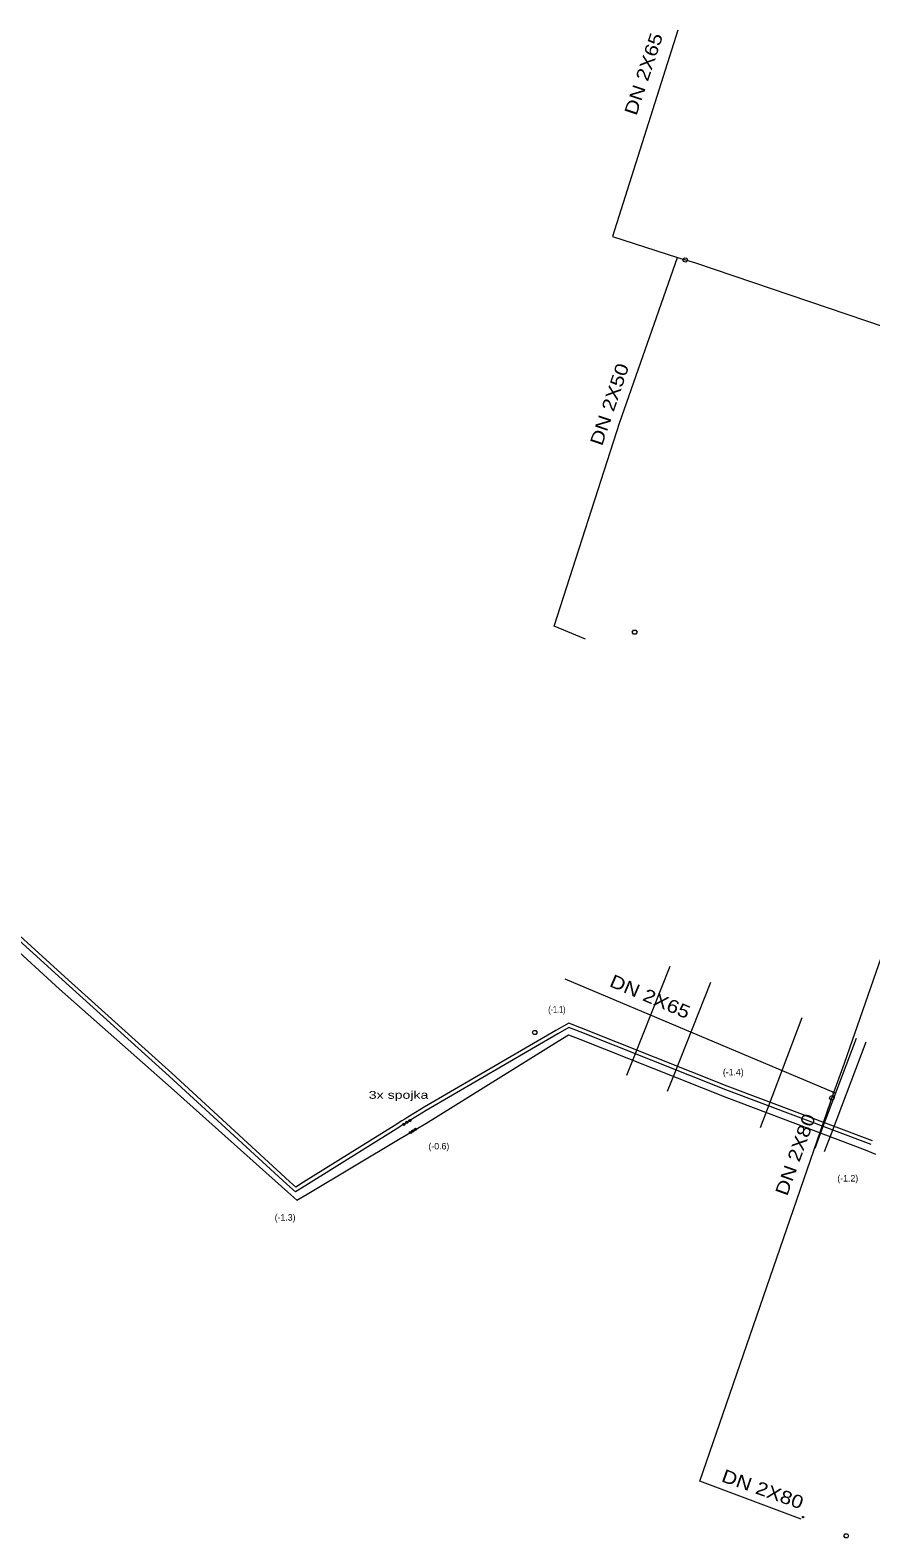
# Model space of a CAD drawing. Extents: x -725606 to -725269, y -977352 to -977136.
# Drawn here: x -725435.3 to -725370.8, y -977352.2 to -977236.5 of the extents above; entities that cross this region are included whole.
import ezdxf
from ezdxf.enums import TextEntityAlignment as Align

# ---------------------------------------------------------------- set-up
doc = ezdxf.new("R2010")
doc.units = 0
doc.header["$LTSCALE"] = 0.2
doc.header["$PDMODE"] = 32
doc.header["$PDSIZE"] = 0.1
for name, color, linetype, lineweight in [('45', 7, 'Continuous', 13), ('47', 7, 'Continuous', 13), ('48', 7, 'Continuous', 13), ('63', 7, 'Continuous', 13)]:
    doc.layers.add(name, color=color, linetype=linetype, lineweight=lineweight)
doc.layers.add('46', color=7, linetype='Continuous')
doc.layers.add('7', color=7, linetype='Continuous')

msp = doc.modelspace()

# ---------------------------------------------------------------- linework, layer by layer
at = {"layer": '45'}
for points in [[(-725379.25, -977320.68), (-725378.72, -977319.28), (-725376.07, -977312.26)], [(-725375.07, -977322.26), (-725374.54, -977320.86), (-725371.89, -977313.85)]]:
    msp.add_lwpolyline(points, dxfattribs=at)
at = {"layer": '47'}
msp.add_lwpolyline([(-725374.34, -977322.54), (-725373.81, -977321.14), (-725371.16, -977314.12)], dxfattribs=at)
at = {"layer": '48'}
for points in [[(-725389.5, -977316.68), (-725388.95, -977315.28), (-725386.19, -977308.31)], [(-725386.38, -977317.91), (-725385.83, -977316.52), (-725383.07, -977309.55)]]:
    msp.add_lwpolyline(points, dxfattribs=at)
at = {"layer": '63'}
for points in [[(-725385.587, -977236.544), (-725390.601, -977252.373), (-725385.627, -977253.982)], [(-725392.672, -977283.251), (-725395.077, -977282.248), (-725390.042, -977266.604), (-725385.627, -977253.982), (-725384.245, -977254.395), (-725355.226, -977264.237)], [(-725373.641, -977318.016), (-725372.809, -977315.746), (-725362.524, -977286.239), (-725361.335, -977286.635), (-725354.58, -977288.386)], [(-725370.76, -977321.99), (-725381.91, -977317.79), (-725393.08, -977313.36), (-725393.94, -977313.02), (-725394.79, -977313.51), (-725404.89, -977319.38), (-725405.55, -977319.79), (-725406.15, -977320.16), (-725406.38, -977320.3), (-725406.6, -977320.44), (-725407.19, -977320.81), (-725414.13, -977325.14), (-725414.92, -977325.63), (-725415.57, -977325.04), (-725424.61, -977316.74), (-725432.8, -977309.35), (-725441.73, -977301.26)], [(-725370.654, -977321.709), (-725381.802, -977317.51), (-725392.97, -977313.081), (-725393.964, -977312.688), (-725394.94, -977313.25), (-725405.045, -977319.123), (-725405.708, -977319.535), (-725406.307, -977319.904), (-725406.539, -977320.045), (-725406.76, -977320.186), (-725407.349, -977320.556), (-725414.288, -977324.885), (-725414.886, -977325.256), (-725415.368, -977324.818), (-725424.408, -977316.518), (-725432.599, -977309.127), (-725441.529, -977301.037)], [(-725441.74, -977302.1), (-725433.01, -977310.07), (-725424.46, -977317.64), (-725415.51, -977325.64), (-725414.81, -977326.26), (-725414.02, -977325.79), (-725406.88, -977321.53), (-725406.1, -977321.07), (-725405.91, -977320.95), (-725405.71, -977320.83), (-725404.93, -977320.37), (-725394.78, -977314.08), (-725393.97, -977313.58), (-725393.11, -977313.92), (-725381.9, -977318.36), (-725371.23, -977322.41), (-725370.43, -977322.72)], [(-725376.137, -977350.717), (-725383.903, -977347.814), (-725373.641, -977318.016), (-725394.234, -977309.306)]]:
    msp.add_lwpolyline(points, dxfattribs=at)
for points in [[(-725385.146, -977254.286), (-725385.197, -977254.119), (-725385.073, -977253.995), (-725384.899, -977254.039), (-725384.848, -977254.206), (-725384.971, -977254.33)], [(-725388.813, -977282.562), (-725388.723, -977282.712), (-725388.813, -977282.862), (-725388.993, -977282.862), (-725389.083, -977282.712), (-725388.993, -977282.562)], [(-725396.476, -977313.258), (-725396.386, -977313.408), (-725396.476, -977313.558), (-725396.656, -977313.558), (-725396.746, -977313.408), (-725396.656, -977313.258)], [(-725373.664, -977318.546), (-725373.835, -977318.584), (-725373.949, -977318.451), (-725373.892, -977318.281), (-725373.721, -977318.243), (-725373.607, -977318.376)], [(-725406.379, -977320.213), (-725406.303, -977320.254), (-725406.303, -977320.342), (-725406.381, -977320.387), (-725406.457, -977320.346), (-725406.457, -977320.258)], [(-725406.149, -977320.073), (-725406.073, -977320.114), (-725406.073, -977320.202), (-725406.151, -977320.247), (-725406.227, -977320.206), (-725406.227, -977320.118)], [(-725406.599, -977320.353), (-725406.523, -977320.394), (-725406.523, -977320.482), (-725406.601, -977320.527), (-725406.677, -977320.486), (-725406.677, -977320.398)], [(-725406.099, -977320.983), (-725406.023, -977321.024), (-725406.023, -977321.112), (-725406.101, -977321.157), (-725406.177, -977321.116), (-725406.177, -977321.028)], [(-725405.909, -977320.863), (-725405.833, -977320.904), (-725405.833, -977320.992), (-725405.911, -977321.037), (-725405.987, -977320.996), (-725405.987, -977320.908)], [(-725405.709, -977320.743), (-725405.633, -977320.784), (-725405.633, -977320.872), (-725405.711, -977320.917), (-725405.787, -977320.876), (-725405.787, -977320.788)], [(-725372.587, -977351.853), (-725372.497, -977352.003), (-725372.587, -977352.153), (-725372.767, -977352.153), (-725372.857, -977352.003), (-725372.767, -977351.853)]]:
    msp.add_lwpolyline(points, close=True, dxfattribs=at)
for p in [(-725373.641, -977318.016), (-725375.99, -977350.56)]:
    msp.add_point(p, dxfattribs=at)

# ---------------------------------------------------------------- texts
at = {"layer": '46', "width": 0.8}
msp.add_text('(-1.1)', height=0.5, dxfattribs=at).set_placement((-725394.87, -977311.88), align=Align.CENTER)
at = {"layer": '46'}
for s, p in [('(-1.4)', (-725381.34, -977316.69)), ('(-0.6)', (-725403.92, -977322.37)), ('(-1.2)', (-725372.56, -977324.83)), ('(-1.3)', (-725415.71, -977327.83))]:
    msp.add_text(s, height=0.5, dxfattribs=at).set_placement(p, align=Align.CENTER)
at = {"layer": '63', "width": 1.2}
for s, rotation, p in [('DN 2X65', 71.562, (-725387.7442, -977240.0611)), ('DN 2X50', 71.276, (-725390.3616, -977265.3945)), ('DN 2X65', 336.956, (-725387.9152, -977311.1067)), ('DN 2X80', 70.187, (-725376.1088, -977322.9335)), ('DN 2X80', 340.566, (-725379.2504, -977348.8904))]:
    msp.add_text(s, height=1, rotation=rotation, dxfattribs=at).set_placement(p, align=Align.CENTER)
at = {"layer": '7', "width": 1.35}
msp.add_text('3x spojka', height=0.6, dxfattribs=at).set_placement((-725407.0085, -977318.487), align=Align.CENTER)

doc.saveas('drawing.dxf')
